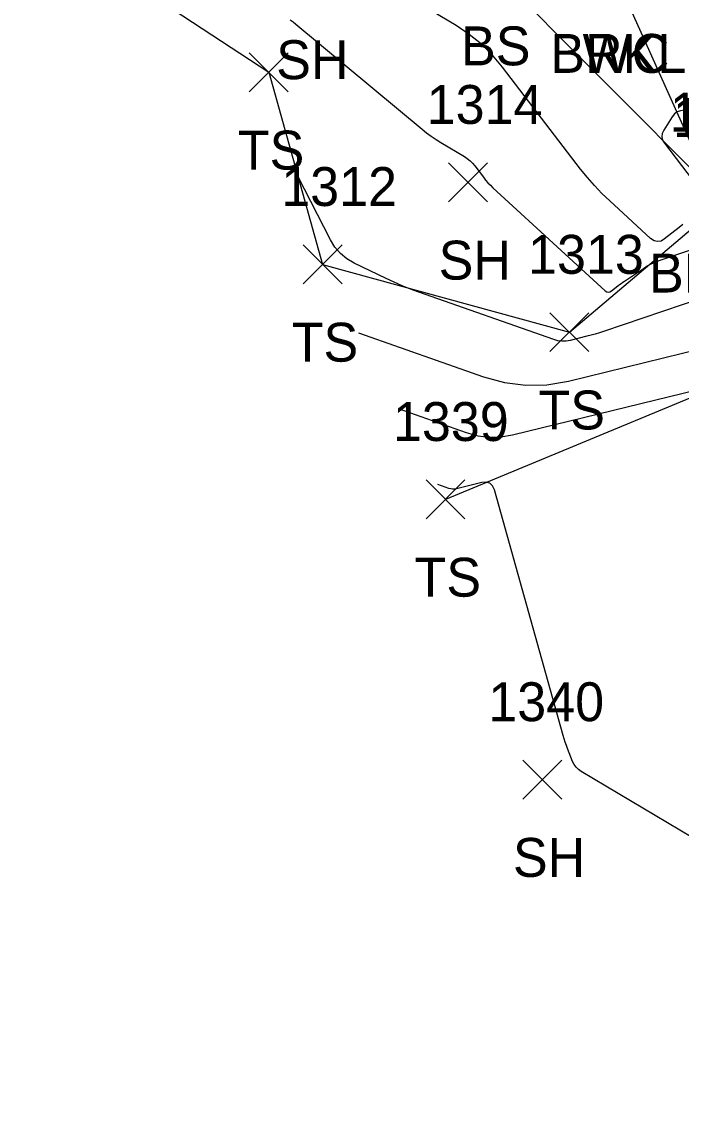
# Model space of a CAD drawing. Extents: x 1592612 to 1596497, y 111838 to 113741.
# Drawn here: x 1592889.5 to 1592923.4, y 113220 to 113275.4 of the extents above; entities that cross this region are included whole.
import ezdxf

# ---------------------------------------------------------------- set-up
doc = ezdxf.new("R2010")
doc.units = 0
for name, color, linetype in [('L_A', 7, 'Continuous'), ('L_I', 7, 'Continuous'), ('L_TIC', 7, 'Continuous'), ('LAWE', 7, 'Continuous'), ('LELB', 7, 'Continuous'), ('LSOGCMA', 7, 'Continuous'), ('LSOGCMI', 7, 'Continuous')]:
    doc.layers.add(name, color=color, linetype=linetype)

msp = doc.modelspace()

# ---------------------------------------------------------------- linework, layer by layer
at = {"layer": 'L_TIC'}
for points in [[(1592901.204, 113271.844), (1592903.204, 113273.844)], [(1592903.204, 113271.844), (1592901.204, 113273.844)], [(1592911.444, 113266.19), (1592913.444, 113268.19)], [(1592913.444, 113266.19), (1592911.444, 113268.19)], [(1592903.97, 113261.973), (1592905.97, 113263.973)], [(1592905.97, 113261.973), (1592903.97, 113263.973)], [(1592916.653, 113258.488), (1592918.653, 113260.488)], [(1592918.653, 113258.488), (1592916.653, 113260.488)], [(1592910.285, 113249.895), (1592912.285, 113251.895)], [(1592912.285, 113249.895), (1592910.285, 113251.895)], [(1592915.264, 113235.494), (1592917.264, 113237.494)], [(1592917.264, 113235.494), (1592915.264, 113237.494)]]:
    msp.add_lwpolyline(points, dxfattribs=at)
at = {"layer": 'LAWE'}
msp.add_lwpolyline([(1592916.07, 113291.076), (1592920.024, 113277.813), (1592925.099, 113266.526)], dxfattribs=at)
at = {"layer": 'LELB'}
for points in [[(1592889.863, 113282.382), (1592901.59, 113280.696), (1592913.642, 113278.201), (1592924.996, 113266.796), (1592943.132, 113254.464), (1592958.132, 113248.138), (1592963.265, 113252.408), (1592986.408, 113242.634)], [(1592889.501, 113281.185), (1592902.204, 113272.845), (1592904.97, 113262.973), (1592917.653, 113259.488), (1592925.476, 113266.102)], [(1592975.857, 113225.25), (1592960.292, 113237.985), (1592946.461, 113244.481), (1592940.546, 113245.09), (1592929.666, 113258.516), (1592911.285, 113250.895)]]:
    msp.add_lwpolyline(points, dxfattribs=at)
at = {"layer": 'LSOGCMA'}
msp.add_lwpolyline([(1592903.297, 113275.539), (1592903.452, 113275.434), (1592903.6, 113275.318), (1592910.085, 113269.919), (1592910.316, 113269.734), (1592910.553, 113269.559), (1592910.797, 113269.392), (1592911.047, 113269.235), (1592912.254, 113268.508), (1592912.405, 113268.407), (1592912.545, 113268.294), (1592912.673, 113268.168), (1592912.79, 113268.029), (1592913.234, 113267.448), (1592913.348, 113267.306), (1592913.468, 113267.169), (1592913.594, 113267.037), (1592913.725, 113266.911), (1592919.495, 113261.616), (1592919.573, 113261.563), (1592919.652, 113261.543), (1592919.733, 113261.557), (1592919.814, 113261.605), (1592920.142, 113261.866), (1592920.225, 113261.93), (1592920.309, 113261.992), (1592920.394, 113262.053), (1592920.48, 113262.113), (1592921.454, 113262.767), (1592921.649, 113262.889), (1592921.85, 113262.997), (1592922.058, 113263.092), (1592922.273, 113263.173), (1592925.208, 113264.17)], dxfattribs=at)
at = {"layer": 'LSOGCMI'}
for points in [[(1592923.477, 113265.018), (1592923.289, 113264.872), (1592922.546, 113264.282), (1592922.362, 113264.173), (1592922.18, 113264.141), (1592922.001, 113264.186), (1592921.825, 113264.308), (1592919.722, 113266.237), (1592919.323, 113266.62), (1592918.941, 113267.02), (1592918.577, 113267.436), (1592918.231, 113267.868), (1592914.217, 113273.113), (1592913.698, 113273.73), (1592913.128, 113274.291), (1592912.508, 113274.794), (1592911.837, 113275.242), (1592908.854, 113277.038)], [(1592923.552, 113270.889), (1592923.361, 113270.871), (1592923.193, 113270.809), (1592923.05, 113270.703), (1592922.93, 113270.553), (1592922.5, 113269.864), (1592922.421, 113269.693), (1592922.4, 113269.525), (1592922.437, 113269.36), (1592922.532, 113269.197), (1592924.283, 113266.909)], [(1592925.46, 113261.581), (1592919.403, 113259.523), (1592919.193, 113259.454), (1592918.981, 113259.39), (1592918.768, 113259.33), (1592918.553, 113259.275), (1592917.693, 113259.065), (1592917.478, 113259.028), (1592917.265, 113259.023), (1592917.054, 113259.049), (1592916.844, 113259.107), (1592909.909, 113261.55), (1592909.483, 113261.706), (1592909.062, 113261.874), (1592908.646, 113262.054), (1592908.235, 113262.246), (1592906.6, 113263.036), (1592906.216, 113263.259), (1592905.883, 113263.534), (1592905.601, 113263.861), (1592905.369, 113264.24), (1592903.7, 113267.505)], [(1592906.807, 113259.459), (1592913.246, 113257.192), (1592914.323, 113256.895), (1592915.408, 113256.76), (1592916.501, 113256.787), (1592917.602, 113256.976), (1592924.449, 113258.648)], [(1592908.847, 113255.559), (1592912.353, 113254.324), (1592912.939, 113254.162), (1592913.53, 113254.089), (1592914.125, 113254.103), (1592914.725, 113254.206), (1592924.964, 113256.706)], [(1592946.777, 113219.954), (1592918.254, 113236.909), (1592918.112, 113237.009), (1592917.993, 113237.128), (1592917.895, 113237.265), (1592917.82, 113237.421), (1592917.562, 113238.083), (1592917.499, 113238.25), (1592917.441, 113238.417), (1592917.387, 113238.586), (1592917.337, 113238.756), (1592913.796, 113251.381), (1592913.704, 113251.591), (1592913.566, 113251.723), (1592913.383, 113251.778), (1592913.155, 113251.756), (1592911.848, 113251.437), (1592911.75, 113251.42), (1592911.652, 113251.417), (1592911.556, 113251.429), (1592911.46, 113251.456), (1592910.887, 113251.658)]]:
    msp.add_lwpolyline(points, dxfattribs=at)

# ---------------------------------------------------------------- texts
at = {"layer": 'L_A'}
for s, p in [('BS', (1592912.083, 113273.201)), ('SH', (1592902.585, 113272.491)), ('BRKL', (1592916.67, 113272.813)), ('WC', (1592918.331, 113272.813)), ('TS', (1592900.613, 113267.844)), ('SH', (1592910.933, 113262.19)), ('BRKL', (1592921.745, 113261.526)), ('TS', (1592903.38, 113257.973)), ('TS', (1592916.063, 113254.488)), ('TS', (1592909.695, 113245.895)), ('SH', (1592914.752, 113231.494))]:
    msp.add_text(s, height=2, dxfattribs=at).set_placement(p)
at = {"layer": 'L_I'}
for s, p in [('1314', (1592910.318, 113270.19)), ('1316', (1592922.815, 113269.796)), ('1317', (1592922.973, 113269.526)), ('1312', (1592902.844, 113265.973)), ('1313', (1592915.528, 113262.488)), ('1339', (1592908.585, 113253.895)), ('1340', (1592913.485, 113239.494))]:
    msp.add_text(s, height=2, dxfattribs=at).set_placement(p)

doc.saveas('drawing.dxf')
